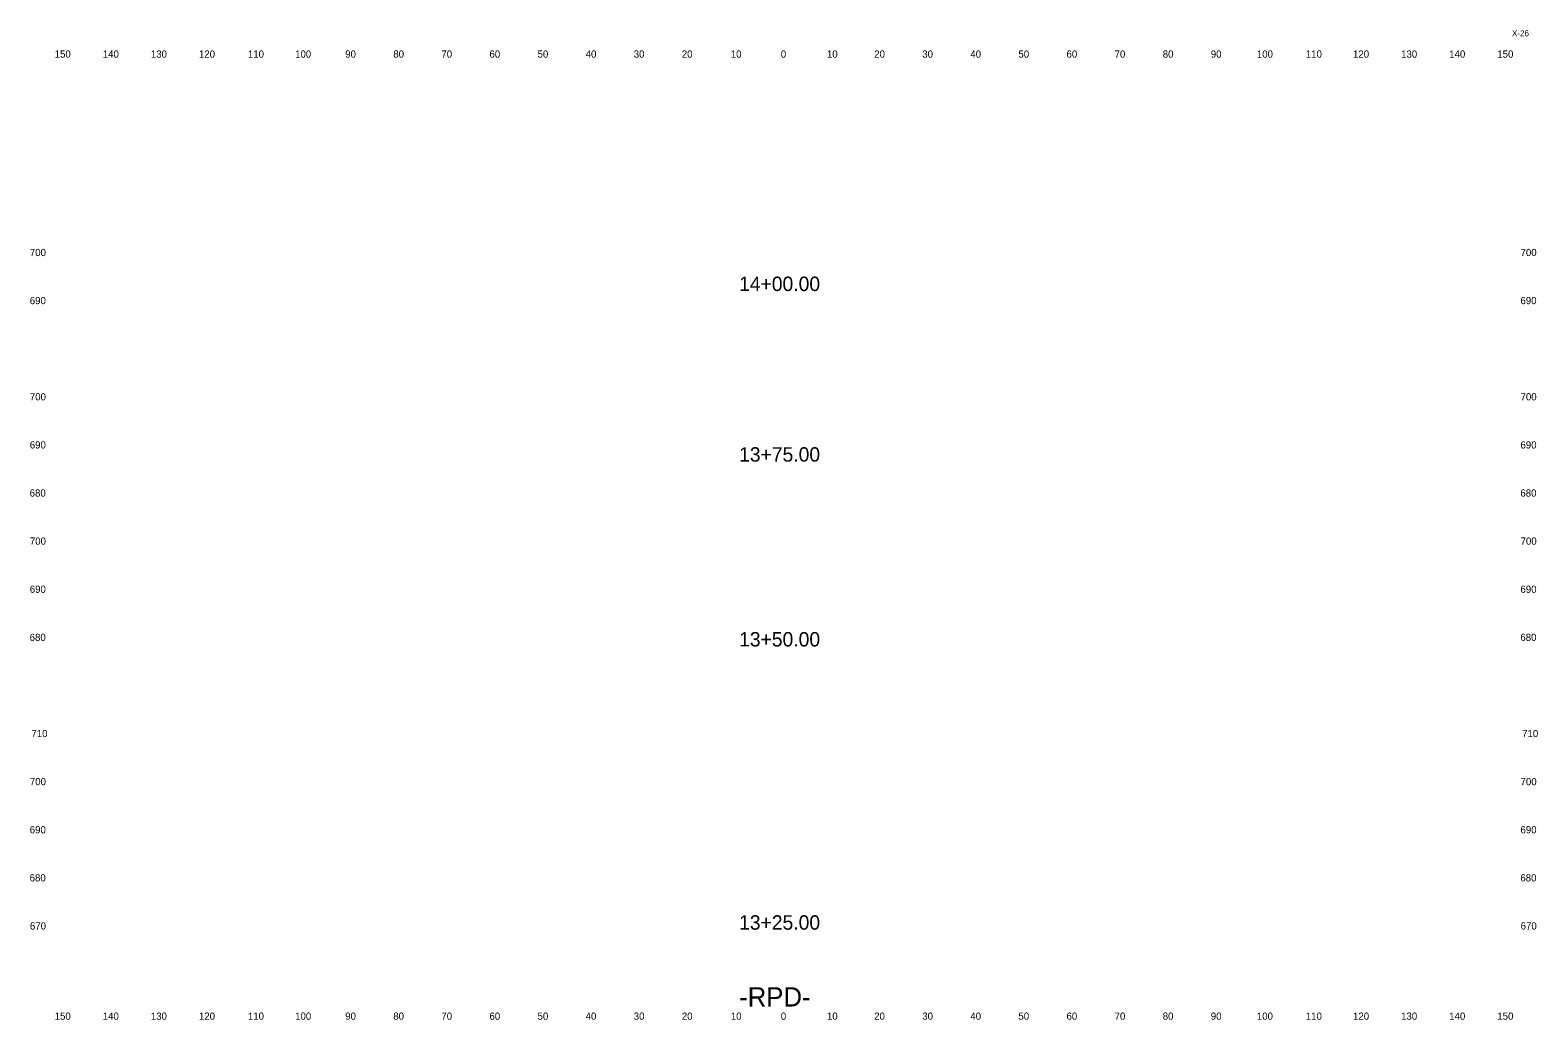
# Model space of a CAD drawing. Extents: x 3 to 317, y 1 to 867.
# Drawn here: x 3.3 to 316.9, y 661.2 to 867 of the extents above; entities that cross this region are included whole.
import ezdxf

# ---------------------------------------------------------------- set-up
doc = ezdxf.new("R2010")
doc.units = 0
for name, color, linetype in [('Prop XS Alignment Label', 7, 'Continuous'), ('Prop XS Elevation Labels', 7, 'Continuous'), ('Prop XS Offset Labels', 7, 'Continuous'), ('Prop XS Sheet Number', 7, 'Continuous'), ('Prop XS Station Labels', 7, 'Continuous')]:
    doc.layers.add(name, color=color, linetype=linetype)

msp = doc.modelspace()

# ---------------------------------------------------------------- texts
at = {"layer": 'Prop XS Alignment Label'}
msp.add_text('-RPD-', height=4, dxfattribs=at).set_placement((150.78, 664))
at = {"layer": 'Prop XS Elevation Labels'}
for s, p in [('700', (3.28, 820)), ('700', (313.28, 820)), ('690', (3.26, 810)), ('690', (313.26, 810)), ('700', (3.28, 790)), ('700', (313.28, 790)), ('690', (3.26, 780)), ('690', (313.26, 780)), ('680', (3.24, 770)), ('680', (313.24, 770)), ('700', (3.28, 760)), ('700', (313.28, 760)), ('690', (3.26, 750)), ('690', (313.26, 750)), ('680', (3.24, 740)), ('680', (313.24, 740)), ('710', (3.61, 720)), ('710', (313.61, 720)), ('700', (3.28, 710)), ('700', (313.28, 710)), ('690', (3.26, 700)), ('690', (313.26, 700)), ('680', (3.24, 690)), ('680', (313.24, 690)), ('670', (3.3, 680)), ('670', (313.3, 680))]:
    msp.add_text(s, height=1.5, dxfattribs=at).set_placement(p)
at = {"layer": 'Prop XS Offset Labels'}
for s, p in [('150', (8.44, 861.25)), ('140', (18.44, 861.25)), ('130', (28.44, 861.25)), ('120', (38.44, 861.25)), ('110', (48.62, 861.25)), ('100', (58.44, 861.25)), ('90', (68.86, 861.25)), ('80', (78.86, 861.25)), ('70', (88.86, 861.25)), ('60', (98.86, 861.25)), ('50', (108.86, 861.25)), ('40', (118.86, 861.25)), ('30', (128.86, 861.25)), ('20', (138.86, 861.25)), ('10', (149.04, 861.25)), ('0', (159.45, 861.25)), ('10', (169.04, 861.25)), ('20', (178.86, 861.25)), ('30', (188.86, 861.25)), ('40', (198.86, 861.25)), ('50', (208.86, 861.25)), ('60', (218.86, 861.25)), ('70', (228.86, 861.25)), ('80', (238.86, 861.25)), ('90', (248.86, 861.25)), ('100', (258.44, 861.25)), ('110', (268.62, 861.25)), ('120', (278.44, 861.25)), ('130', (288.44, 861.25)), ('140', (298.44, 861.25)), ('150', (308.44, 861.25)), ('150', (8.44, 661.25)), ('140', (18.44, 661.25)), ('130', (28.44, 661.25)), ('120', (38.44, 661.25)), ('110', (48.62, 661.25)), ('100', (58.44, 661.25)), ('90', (68.86, 661.25)), ('80', (78.86, 661.25)), ('70', (88.86, 661.25)), ('60', (98.86, 661.25)), ('50', (108.86, 661.25)), ('40', (118.86, 661.25)), ('30', (128.86, 661.25)), ('20', (138.86, 661.25)), ('10', (149.04, 661.25)), ('0', (159.45, 661.25)), ('10', (169.04, 661.25)), ('20', (178.86, 661.25)), ('30', (188.86, 661.25)), ('40', (198.86, 661.25)), ('50', (208.86, 661.25)), ('60', (218.86, 661.25)), ('70', (228.86, 661.25)), ('80', (238.86, 661.25)), ('90', (248.86, 661.25)), ('100', (258.44, 661.25)), ('110', (268.62, 661.25)), ('120', (278.44, 661.25)), ('130', (288.44, 661.25)), ('140', (298.44, 661.25)), ('150', (308.44, 661.25))]:
    msp.add_text(s, height=1.5, dxfattribs=at).set_placement(p)
at = {"layer": 'Prop XS Sheet Number'}
msp.add_text('X-26', height=1.25, dxfattribs=at).set_placement((311.5, 865.7))
at = {"layer": 'Prop XS Station Labels'}
for s, p in [('14+00.00', (150.77, 812.73)), ('13+75.00', (150.77, 777.27)), ('13+50.00', (150.77, 738.84)), ('13+25.00', (150.77, 679.97))]:
    msp.add_text(s, height=3, dxfattribs=at).set_placement(p)

doc.saveas('drawing.dxf')
